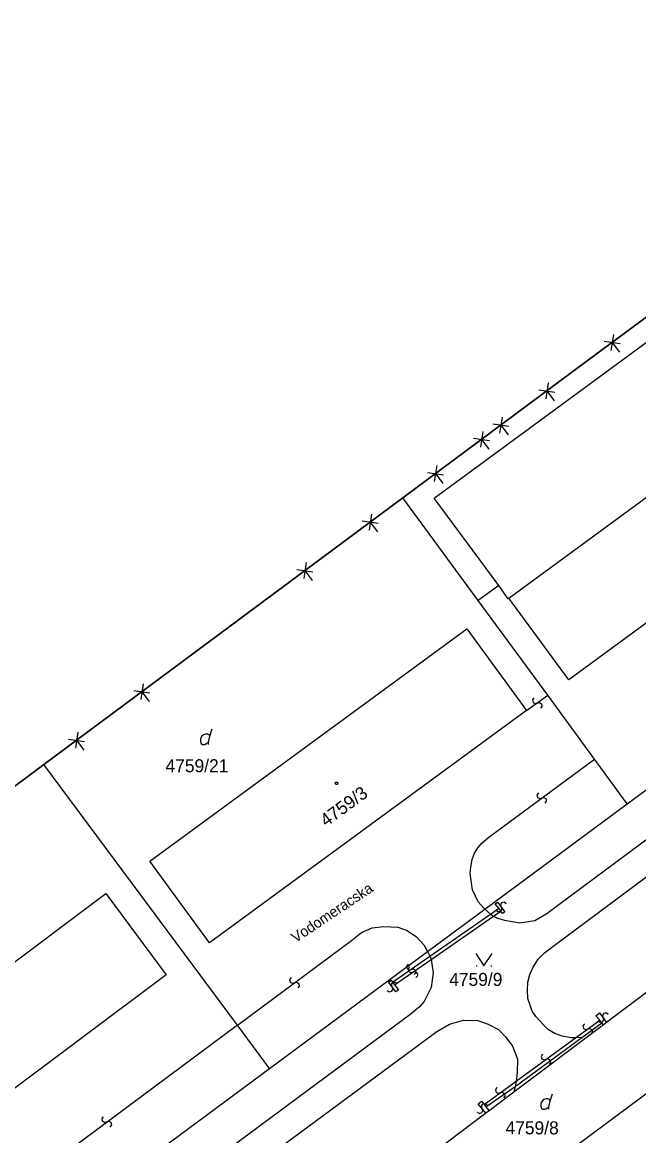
# Model space of a CAD drawing. Extents: x -266179 to -264727, y -1243225 to -1241702.
# Drawn here: x -265584.5 to -265508.7, y -1242990.2 to -1242853.4 of the extents above; entities that cross this region are included whole.
import ezdxf

# ---------------------------------------------------------------- set-up
doc = ezdxf.new("R2010")
doc.units = 0
for name, color, linetype in [('Vrstva 1', 7, 'Continuous'), ('Vrstva 2', 7, 'Continuous'), ('Vrstva 21', 7, 'Continuous'), ('Vrstva 22', 7, 'Continuous')]:
    doc.layers.add(name, color=color, linetype=linetype)

msp = doc.modelspace()

# ---------------------------------------------------------------- linework, layer by layer
at = {"layer": 'Vrstva 1'}
for p, q in [((-265515.95, -1242895.72), (-265457.68, -1242852.47)), ((-265533.81, -1242911.88), (-265470.99, -1242865.69)), ((-265537.67, -1242911.84), (-265515.95, -1242895.72)), ((-265524.63, -1242924.18), (-265485.75, -1242895.63)), ((-265478.33, -1242905.64), (-265517.27, -1242934.21)), ((-265581.81, -1242944.61), (-265537.67, -1242911.84)), ((-265528.4, -1242924.47), (-265537.67, -1242911.84)), ((-265525.89, -1242922.63), (-265533.81, -1242911.88)), ((-265525.89, -1242922.63), (-265528.4, -1242924.47)), ((-265524.71, -1242924.24), (-265525.89, -1242922.63)), ((-265510.08, -1242949.43), (-265473.9, -1242922.67)), ((-265519.86, -1242936.1), (-265528.4, -1242924.47)), ((-265524.63, -1242924.18), (-265524.71, -1242924.24)), ((-265517.27, -1242934.21), (-265524.63, -1242924.18)), ((-265568.79, -1242956.51), (-265529.81, -1242927.96)), ((-265529.81, -1242927.96), (-265522.46, -1242938)), ((-265514.1, -1242943.95), (-265519.86, -1242936.1)), ((-265522.46, -1242938), (-265561.45, -1242966.53)), ((-265561.39, -1242941.15), (-265561.12, -1242940.25)), ((-265510.08, -1242949.43), (-265514.1, -1242943.95)), ((-265609.42, -1242965.11), (-265581.81, -1242944.61)), ((-265558.02, -1242976.64), (-265581.81, -1242944.61)), ((-265527.6, -1242962.38), (-265510.08, -1242949.43)), ((-265561.45, -1242966.53), (-265568.79, -1242956.51)), ((-265612.83, -1242989.37), (-265574.21, -1242960.48)), ((-265574.21, -1242960.48), (-265566.78, -1242970.48)), ((-265534.65, -1242967.6), (-265527.6, -1242962.38)), ((-265554.07, -1242981.96), (-265534.65, -1242967.6)), ((-265501.08, -1242967.63), (-265512.63, -1242976.32)), ((-265566.78, -1242970.48), (-265605.43, -1242999.37)), ((-265528.65, -1242969.36), (-265528.55, -1242969.36)), ((-265526.85, -1242969.36), (-265526.75, -1242969.36)), ((-265495.14, -1242975.72), (-265534.92, -1243005.24)), ((-265554.07, -1242981.96), (-265558.02, -1242976.64)), ((-265513.01, -1242976.6), (-265524.03, -1242984.89)), ((-265512.63, -1242976.32), (-265513.01, -1242976.6)), ((-265587.32, -1243006.56), (-265554.07, -1242981.96)), ((-265524.03, -1242984.89), (-265527.06, -1242987.17)), ((-265519.55, -1242985.98), (-265519.28, -1242985.08)), ((-265527.45, -1242987.46), (-265540.57, -1242997.33)), ((-265527.06, -1242987.17), (-265527.45, -1242987.46))]:
    msp.add_line(p, q, dxfattribs=at)
for points in [[(-265561.57, -1242942.14), (-265561.57, -1242941.87), (-265561.39, -1242941.15), (-265561.48, -1242940.97), (-265561.66, -1242940.88), (-265561.93, -1242940.88), (-265562.2, -1242940.97), (-265562.38, -1242941.15), (-265562.56, -1242941.42), (-265562.56, -1242941.78), (-265562.47, -1242942.05), (-265562.29, -1242942.14), (-265562.02, -1242942.14), (-265561.84, -1242942.05), (-265561.57, -1242941.87)], [(-265528.7, -1242967.86), (-265527.7, -1242969.36), (-265526.7, -1242967.86)], [(-265519.73, -1242986.97), (-265519.73, -1242986.7), (-265519.55, -1242985.98), (-265519.64, -1242985.8), (-265519.82, -1242985.71), (-265520.09, -1242985.71), (-265520.36, -1242985.8), (-265520.54, -1242985.98), (-265520.72, -1242986.25), (-265520.72, -1242986.61), (-265520.63, -1242986.88), (-265520.45, -1242986.97), (-265520.18, -1242986.97), (-265520, -1242986.88), (-265519.73, -1242986.7)]]:
    msp.add_lwpolyline(points, dxfattribs=at)
msp.add_lwpolyline([(-265545.73, -1242946.78), (-265545.64, -1242946.93), (-265545.73, -1242947.08), (-265545.91, -1242947.08), (-265546, -1242946.93), (-265545.91, -1242946.78)], close=True, dxfattribs=at)
at = {"layer": 'Vrstva 2'}
for p, q in [((-265519.07, -1242966.85), (-265474.69, -1242933.88)), ((-265522.46, -1242938), (-265519.86, -1242936.1)), ((-265518.51, -1242961.83), (-265490.38, -1242940.92)), ((-265527.11, -1242953.53), (-265514.1, -1242943.95)), ((-265527.93, -1242954.24), (-265527.11, -1242953.53)), ((-265529.16, -1242956.31), (-265528.85, -1242955.52)), ((-265528.85, -1242955.52), (-265528.46, -1242954.86)), ((-265528.46, -1242954.86), (-265527.93, -1242954.24)), ((-265529.31, -1242957.25), (-265529.16, -1242956.31)), ((-265529.38, -1242958.01), (-265529.31, -1242957.25)), ((-265529.25, -1242959.18), (-265529.38, -1242958.01)), ((-265529.1, -1242960), (-265529.25, -1242959.18)), ((-265528.73, -1242960.79), (-265529.1, -1242960)), ((-265528.43, -1242961.48), (-265528.73, -1242960.79)), ((-265527.68, -1242962.31), (-265528.43, -1242961.48)), ((-265527.6, -1242962.38), (-265527.68, -1242962.31)), ((-265527.6, -1242962.38), (-265526.91, -1242962.99)), ((-265526.91, -1242962.99), (-265525.89, -1242962.29)), ((-265526.31, -1242961.73), (-265526.04, -1242961.52)), ((-265525.89, -1242962.29), (-265526.31, -1242961.73)), ((-265526.04, -1242961.52), (-265525.14, -1242962.74)), ((-265525.64, -1242962.63), (-265525.89, -1242962.29)), ((-265519.97, -1242962.91), (-265518.51, -1242961.83)), ((-265534.36, -1242968.19), (-265526.91, -1242962.99)), ((-265534.2, -1242968.57), (-265526.52, -1242963.24)), ((-265526.91, -1242962.99), (-265526.52, -1242963.24)), ((-265526.52, -1242963.24), (-265525.64, -1242962.63)), ((-265526.52, -1242963.24), (-265526.02, -1242963.52)), ((-265526.02, -1242963.52), (-265525.19, -1242963.75)), ((-265525.41, -1242962.94), (-265525.64, -1242962.63)), ((-265525.14, -1242962.74), (-265525.41, -1242962.94)), ((-265525.19, -1242963.75), (-265523.29, -1242964.08)), ((-265521.46, -1242963.78), (-265519.97, -1242962.91)), ((-265542.75, -1242965.25), (-265541.44, -1242964.71)), ((-265541.44, -1242964.71), (-265540.02, -1242964.51)), ((-265540.02, -1242964.51), (-265538.28, -1242964.61)), ((-265538.28, -1242964.61), (-265537.15, -1242965.01)), ((-265537.15, -1242965.01), (-265535.99, -1242965.78)), ((-265523.29, -1242964.08), (-265521.46, -1242963.78)), ((-265558.02, -1242976.64), (-265544, -1242966.23)), ((-265544, -1242966.23), (-265542.75, -1242965.25)), ((-265535.99, -1242965.78), (-265535.11, -1242966.79)), ((-265535.11, -1242966.79), (-265534.69, -1242967.51)), ((-265534.69, -1242967.51), (-265534.65, -1242967.6)), ((-265534.65, -1242967.6), (-265534.36, -1242968.19)), ((-265521.03, -1242968.52), (-265520.24, -1242967.76)), ((-265520.24, -1242967.76), (-265519.07, -1242966.85)), ((-265538.94, -1242971.37), (-265534.36, -1242968.19)), ((-265538.7, -1242971.69), (-265534.2, -1242968.57)), ((-265534.36, -1242968.19), (-265534.2, -1242968.57)), ((-265534.2, -1242968.57), (-265533.95, -1242970.22)), ((-265521.63, -1242969.52), (-265521.03, -1242968.52)), ((-265533.95, -1242970.22), (-265534.21, -1242972.04)), ((-265522.3, -1242971.36), (-265522.04, -1242970.42)), ((-265522.04, -1242970.42), (-265521.63, -1242969.52)), ((-265539.45, -1242971.37), (-265539.13, -1242971.13)), ((-265538.54, -1242972.54), (-265539.45, -1242971.37)), ((-265539.13, -1242971.13), (-265538.94, -1242971.37)), ((-265538.94, -1242971.37), (-265538.7, -1242971.69)), ((-265538.7, -1242971.69), (-265538.22, -1242972.29)), ((-265522.35, -1242972.35), (-265522.3, -1242971.36)), ((-265538.22, -1242972.29), (-265538.54, -1242972.54)), ((-265534.21, -1242972.04), (-265535.04, -1242973.75)), ((-265522.29, -1242973.36), (-265522.35, -1242972.35)), ((-265535.62, -1242974.39), (-265536.64, -1242975.25)), ((-265535.04, -1242973.75), (-265535.62, -1242974.39)), ((-265522.07, -1242974.08), (-265522.29, -1242973.36)), ((-265521.79, -1242974.92), (-265522.07, -1242974.08)), ((-265536.64, -1242975.25), (-265584.1, -1243010.38)), ((-265531.93, -1242976.54), (-265530.22, -1242976.04)), ((-265530.22, -1242976.04), (-265528.47, -1242976.08)), ((-265521.32, -1242975.6), (-265521.79, -1242974.92)), ((-265520.37, -1242976.61), (-265521.32, -1242975.6)), ((-265516.45, -1242978.19), (-265513.44, -1242976.05)), ((-265513.94, -1242975.49), (-265513.5, -1242975.14)), ((-265513.44, -1242976.05), (-265513.94, -1242975.49)), ((-265513.5, -1242975.14), (-265512.63, -1242976.32)), ((-265513.2, -1242976.35), (-265513.44, -1242976.05)), ((-265558.02, -1242976.64), (-265590.1, -1243000.48)), ((-265533.51, -1242977.45), (-265531.93, -1242976.54)), ((-265528.47, -1242976.08), (-265527.17, -1242976.54)), ((-265527.17, -1242976.54), (-265525.92, -1242977.2)), ((-265525.92, -1242977.2), (-265525, -1242978.12)), ((-265519.75, -1242977.21), (-265520.37, -1242976.61)), ((-265518.97, -1242977.67), (-265519.75, -1242977.21)), ((-265515.68, -1242978.17), (-265513.2, -1242976.35)), ((-265513.01, -1242976.6), (-265513.2, -1242976.35)), ((-265582.02, -1243013.24), (-265533.51, -1242977.45)), ((-265525, -1242978.12), (-265524.2, -1242979.25)), ((-265523.88, -1242984.2), (-265515.68, -1242978.17)), ((-265523.72, -1242983.52), (-265516.45, -1242978.19)), ((-265518.07, -1242977.99), (-265518.97, -1242977.67)), ((-265516.99, -1242978.19), (-265518.07, -1242977.99)), ((-265516.45, -1242978.19), (-265516.99, -1242978.19)), ((-265515.68, -1242978.17), (-265516.45, -1242978.19)), ((-265524.2, -1242979.25), (-265523.58, -1242980.83)), ((-265523.58, -1242980.83), (-265523.62, -1242982.46)), ((-265523.62, -1242982.46), (-265523.72, -1242983.52)), ((-265527.68, -1242986.41), (-265523.72, -1242983.52)), ((-265527.46, -1242986.68), (-265523.88, -1242984.2)), ((-265523.88, -1242984.2), (-265524.03, -1242984.89)), ((-265523.72, -1242983.52), (-265523.88, -1242984.2)), ((-265528.4, -1242986.31), (-265528.02, -1242985.99)), ((-265527.45, -1242987.46), (-265528.4, -1242986.31)), ((-265528.02, -1242985.99), (-265527.68, -1242986.41)), ((-265527.68, -1242986.41), (-265527.46, -1242986.68)), ((-265527.46, -1242986.68), (-265527.06, -1242987.17)), ((-265527.06, -1242987.17), (-265527.45, -1242987.46))]:
    msp.add_line(p, q, dxfattribs=at)
for points in [[(-265521.562, -1242936.415), (-265521.748, -1242936.687), (-265521.659, -1242936.994), (-265521.399, -1242937.113), (-265520.877, -1242936.98), (-265520.619, -1242937.163), (-265520.589, -1242937.475), (-265520.758, -1242937.685)], [(-265521.01, -1242948.107), (-265521.194, -1242948.379), (-265521.105, -1242948.686), (-265520.844, -1242948.804), (-265520.322, -1242948.668), (-265520.064, -1242948.851), (-265520.033, -1242949.163), (-265520.2, -1242949.373)], [(-265524.957, -1242961.725), (-265525.229, -1242961.541), (-265525.536, -1242961.63), (-265525.654, -1242961.891), (-265525.518, -1242962.413), (-265525.7, -1242962.671), (-265526.013, -1242962.703), (-265526.223, -1242962.535)], [(-265537.037, -1242969.135), (-265537.229, -1242969.403), (-265537.148, -1242969.712), (-265536.89, -1242969.837), (-265536.365, -1242969.716), (-265536.112, -1242969.906), (-265536.09, -1242970.219), (-265536.263, -1242970.425)], [(-265536.836, -1242969.485), (-265537.028, -1242969.752), (-265536.948, -1242970.061), (-265536.69, -1242970.187), (-265536.165, -1242970.067), (-265535.912, -1242970.256), (-265535.89, -1242970.569), (-265536.064, -1242970.775)], [(-265551.417, -1242970.803), (-265551.6, -1242971.076), (-265551.51, -1242971.383), (-265551.248, -1242971.5), (-265550.728, -1242971.362), (-265550.468, -1242971.543), (-265550.436, -1242971.856), (-265550.603, -1242972.067)], [(-265539.618, -1242972.376), (-265539.34, -1242972.553), (-265539.036, -1242972.456), (-265538.925, -1242972.192), (-265539.074, -1242971.674), (-265538.899, -1242971.411), (-265538.587, -1242971.372), (-265538.372, -1242971.534)], [(-265512.432, -1242975.325), (-265512.704, -1242975.141), (-265513.011, -1242975.23), (-265513.129, -1242975.491), (-265512.993, -1242976.013), (-265513.175, -1242976.271), (-265513.488, -1242976.303), (-265513.698, -1242976.135)], [(-265515.339, -1242976.48), (-265515.528, -1242976.749), (-265515.444, -1242977.057), (-265515.185, -1242977.18), (-265514.661, -1242977.053), (-265514.406, -1242977.24), (-265514.38, -1242977.553), (-265514.551, -1242977.76)], [(-265520.488, -1242980.221), (-265520.673, -1242980.493), (-265520.584, -1242980.8), (-265520.324, -1242980.918), (-265519.802, -1242980.784), (-265519.544, -1242980.967), (-265519.513, -1242981.279), (-265519.682, -1242981.489)], [(-265526.101, -1242984.33), (-265526.287, -1242984.601), (-265526.199, -1242984.908), (-265525.939, -1242985.028), (-265525.417, -1242984.895), (-265525.159, -1242985.078), (-265525.13, -1242985.391), (-265525.299, -1242985.6)], [(-265528.535, -1242987.324), (-265528.253, -1242987.493), (-265527.952, -1242987.387), (-265527.848, -1242987.12), (-265528.012, -1242986.607), (-265527.844, -1242986.339), (-265527.534, -1242986.29), (-265527.315, -1242986.446)], [(-265573.653, -1242989.192), (-265573.469, -1242988.918), (-265573.56, -1242988.612), (-265573.822, -1242988.495), (-265574.342, -1242988.633), (-265574.602, -1242988.452), (-265574.634, -1242988.14), (-265574.467, -1242987.928)]]:
    msp.add_lwpolyline(points, dxfattribs=at)
at = {"layer": 'Vrstva 21'}
for p, q in [((-265515.95, -1242895.72), (-265457.68, -1242852.47)), ((-265457.68, -1242852.47), (-265515.95, -1242895.72)), ((-265511.789, -1242891.763), (-265512.078, -1242893.721)), ((-265512.913, -1242892.598), (-265510.954, -1242892.886)), ((-265511.934, -1242892.742), (-265511.039, -1242893.946)), ((-265537.67, -1242911.84), (-265515.95, -1242895.72)), ((-265515.95, -1242895.72), (-265537.67, -1242911.84)), ((-265519.818, -1242897.723), (-265520.109, -1242899.681)), ((-265520.943, -1242898.556), (-265518.984, -1242898.847)), ((-265519.964, -1242898.702), (-265519.07, -1242899.907)), ((-265525.478, -1242901.923), (-265525.769, -1242903.882)), ((-265526.603, -1242902.757), (-265524.644, -1242903.048)), ((-265525.623, -1242902.902), (-265524.73, -1242904.107)), ((-265528.976, -1242904.512), (-265527.017, -1242904.803)), ((-265527.851, -1242903.678), (-265528.142, -1242905.637)), ((-265527.997, -1242904.658), (-265527.103, -1242905.863)), ((-265534.636, -1242908.713), (-265532.677, -1242909.004)), ((-265533.511, -1242907.879), (-265533.802, -1242909.837)), ((-265533.656, -1242908.858), (-265532.763, -1242910.063)), ((-265581.81, -1242944.61), (-265537.67, -1242911.84)), ((-265537.67, -1242911.84), (-265581.81, -1242944.61)), ((-265541.541, -1242913.84), (-265541.83, -1242915.798)), ((-265542.665, -1242914.675), (-265540.706, -1242914.963)), ((-265541.686, -1242914.819), (-265540.791, -1242916.023)), ((-265549.568, -1242919.804), (-265549.857, -1242921.762)), ((-265550.692, -1242920.638), (-265548.733, -1242920.927)), ((-265549.713, -1242920.783), (-265548.818, -1242921.987)), ((-265569.623, -1242934.688), (-265569.912, -1242936.646)), ((-265570.747, -1242935.523), (-265568.788, -1242935.812)), ((-265569.767, -1242935.667), (-265568.873, -1242936.871)), ((-265578.774, -1242941.487), (-265576.815, -1242941.775)), ((-265577.65, -1242940.652), (-265577.939, -1242942.61)), ((-265577.794, -1242941.631), (-265576.9, -1242942.835)), ((-265609.42, -1242965.11), (-265581.81, -1242944.61)), ((-265581.81, -1242944.61), (-265609.42, -1242965.11))]:
    msp.add_line(p, q, dxfattribs=at)

# ---------------------------------------------------------------- texts
at = {"layer": 'Vrstva 1'}
for s, p in [('4759/21', (-265566.858, -1242945.57)), ('4759/9', (-265531.976, -1242971.83)), ('4759/8', (-265525.049, -1242990.07))]:
    msp.add_text(s, height=1.6, dxfattribs=at).set_placement(p)
msp.add_text('4759/3', height=1.6, rotation=36.21093, dxfattribs=at).set_placement((-265547.108, -1242952.334))
at = {"layer": 'Vrstva 22'}
msp.add_text('Vodomeracska', height=1.3, rotation=33.80451, dxfattribs=at).set_placement((-265550.853, -1242966.585))

doc.saveas('drawing.dxf')
